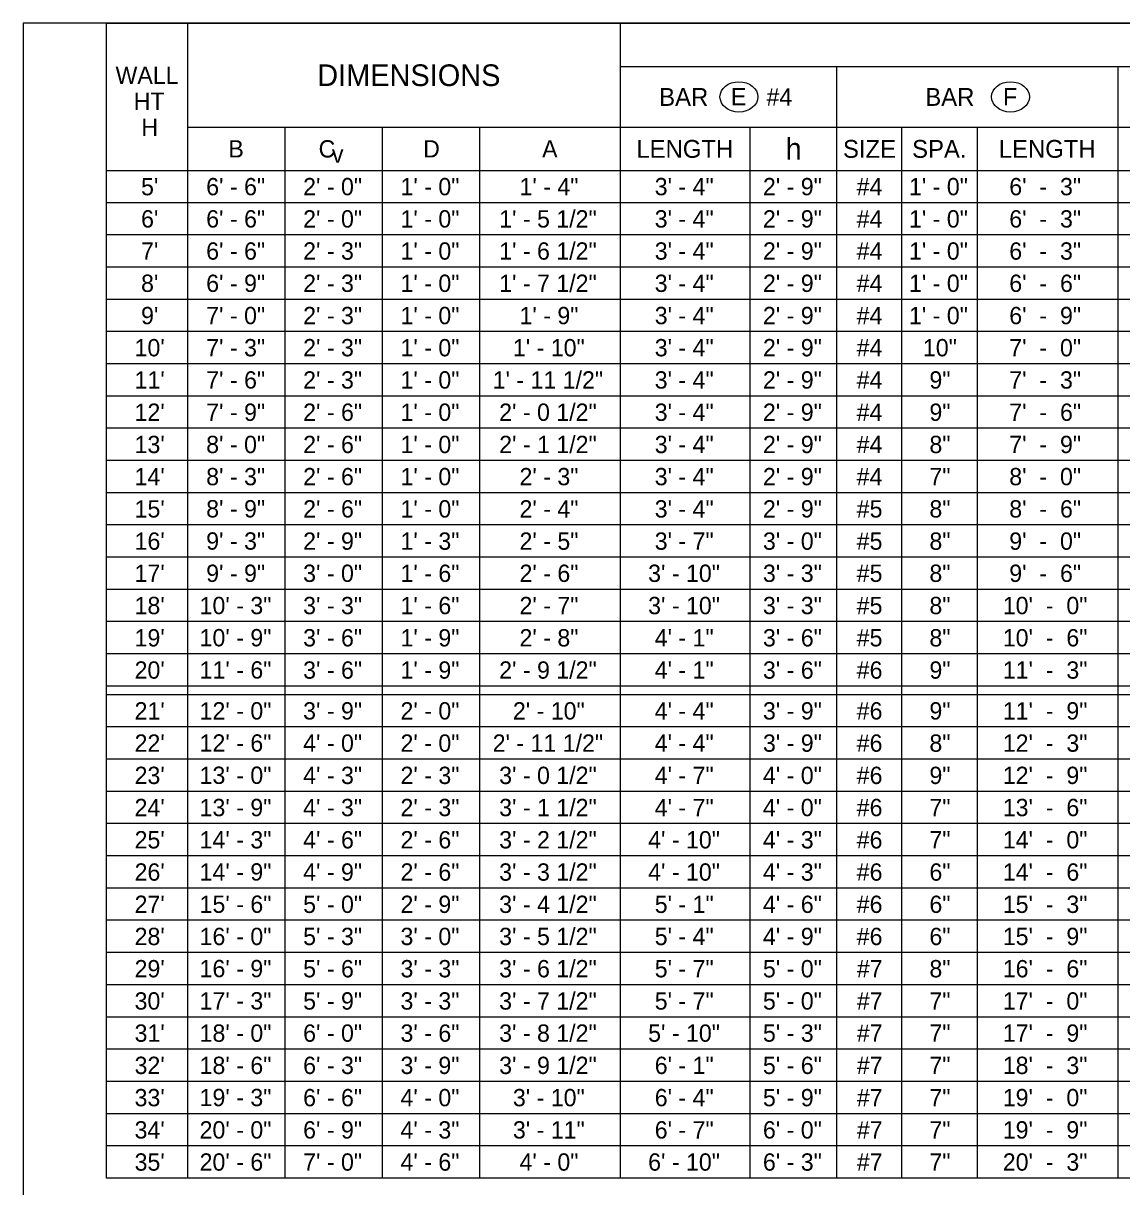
# Model space of a CAD drawing. Extents: x 99862 to 103151, y 100000 to 105076.
# Drawn here: x 99862 to 100877, y 104001 to 105076 of the extents above; entities that cross this region are included whole.
import ezdxf

# ---------------------------------------------------------------- set-up
doc = ezdxf.new("R2010")
doc.units = 0
for name, color, linetype in [('Level 1', 7, 'Continuous'), ('Level 20', 7, 'Continuous'), ('Level 4', 7, 'Continuous')]:
    doc.layers.add(name, color=color, linetype=linetype)

msp = doc.modelspace()

# ---------------------------------------------------------------- linework, layer by layer
at = {"layer": 'Level 1'}
msp.add_lwpolyline([(99862, 102999.5), (103151, 102999.5), (103151, 105075.5), (99862, 105075.5)], close=True, dxfattribs=at)
at = {"layer": 'Level 20'}
for centre in [(100523.5, 105007.5), (100774.5, 105007.5)]:
    msp.add_ellipse(centre, major_axis=(-17.5, 0), ratio=0.8, dxfattribs=at)
at = {"layer": 'Level 4'}
for p, q in [((100014, 104008.6), (100014, 105075.5)), ((100414, 104008.6), (100414, 105075.5)), ((100414, 105035.5), (102554, 105035.5)), ((100614, 104008.6), (100614, 105035.5)), ((100874, 104008.6), (100874, 105035.5)), ((100014, 104979.5), (102711, 104979.5)), ((100104, 104008.6), (100104, 104979.5)), ((100194, 104008.6), (100194, 104979.5)), ((100284, 104008.6), (100284, 104979.5)), ((100534, 104008.6), (100534, 104979.5)), ((100674, 104008.6), (100674, 104979.5)), ((100744, 104008.6), (100744, 104979.5)), ((99939, 104939.5), (103151, 104939.5)), ((103151, 104909.7), (99939, 104909.7)), ((103151, 104880), (99939, 104880)), ((103151, 104850.2), (99939, 104850.2)), ((103151, 104820.4), (99939, 104820.4)), ((103151, 104790.6), (99939, 104790.6)), ((103151, 104760.9), (99939, 104760.9)), ((103151, 104731.1), (99939, 104731.1)), ((103151, 104701.3), (99939, 104701.3)), ((103151, 104671.6), (99939, 104671.6)), ((103151, 104641.8), (99939, 104641.8)), ((103151, 104612), (99939, 104612)), ((103151, 104582.2), (99939, 104582.2)), ((103151, 104552.5), (99939, 104552.5)), ((103151, 104522.7), (99939, 104522.7)), ((103151, 104492.9), (99939, 104492.9)), ((103151, 104463.2), (99939, 104463.2)), ((103151, 104455.2), (99939, 104455.2)), ((103151, 104425.4), (99939, 104425.4)), ((103151, 104395.6), (99939, 104395.6)), ((103151, 104365.8), (99939, 104365.8)), ((103151, 104336.1), (99939, 104336.1)), ((103151, 104306.3), (99939, 104306.3)), ((103151, 104276.5), (99939, 104276.5)), ((103151, 104246.8), (99939, 104246.8)), ((103151, 104217), (99939, 104217)), ((103151, 104187.2), (99939, 104187.2)), ((103151, 104157.4), (99939, 104157.4)), ((103151, 104127.7), (99939, 104127.7)), ((103151, 104097.9), (99939, 104097.9)), ((103151, 104068.1), (99939, 104068.1)), ((103151, 104038.4), (99939, 104038.4))]:
    msp.add_line(p, q, dxfattribs=at)
for points in [[(99939, 105075.5), (103151, 105075.5)], [(103151, 104008.6), (99939, 104008.6), (99939, 105075.5)]]:
    msp.add_lwpolyline(points, dxfattribs=at)

# ---------------------------------------------------------------- texts
at = {"layer": 'Level 20'}
for s, height, p in [('WALL', 16, (99947.3, 105019.5)), ('DIMENSIONS', 20, (100133.7, 105017.5)), ('HT', 16, (99964.1, 104995.5)), ('BAR', 16.5, (100449.8, 104999.2)), ('E', 16, (100516.1, 104999.7)), ('#4', 16, (100549, 104999.5)), ('BAR', 16.5, (100695.8, 104999.2)), ('F', 16, (100767.7, 104999.7)), ('H', 16, (99971.2, 104971.5)), ('C', 16, (100135, 104951.5)), ('LENGTH', 16.5, (100428.7, 104951.2)), ('h', 20, (100566.6, 104949.5)), ('SIZE', 16.5, (100619.7, 104951.2)), ('SPA.', 16.5, (100683.6, 104951.2)), ('LENGTH', 16.5, (100763.7, 104951.2)), ('B', 16, (100051.6, 104951.5)), ('v', 16, (100147.3, 104946.6)), ('D', 16, (100231.6, 104951.5)), ('A', 16, (100341.6, 104951.5)), ("5'", 16, (99970.9, 104916.6)), ('6\' - 6"', 16, (100031.1, 104916.6)), ('2\' - 0"', 16, (100120.7, 104916.6)), ('1\' - 0"', 16, (100210.7, 104916.6)), ('1\' - 4"', 16, (100320.7, 104916.6)), ('2\' - 9"', 16, (100545.7, 104916.6)), ('1\' - 5 1/2"', 16, (100301.9, 104886.8)), ("6'", 16, (99970.9, 104886.8)), ('6\' - 6"', 16, (100031.1, 104886.8)), ('2\' - 0"', 16, (100120.7, 104886.8)), ('1\' - 0"', 16, (100210.7, 104886.8)), ('2\' - 9"', 16, (100545.7, 104886.8)), ("7'", 16, (99970.9, 104857.1)), ('6\' - 6"', 16, (100031.1, 104857.1)), ('2\' - 3"', 16, (100120.7, 104857.1)), ('1\' - 0"', 16, (100210.7, 104857.1)), ('1\' - 6 1/2"', 16, (100301.9, 104857.1)), ('2\' - 9"', 16, (100545.7, 104857.1)), ("8'", 16, (99970.9, 104827.3)), ('6\' - 9"', 16, (100031.1, 104827.3)), ('2\' - 3"', 16, (100120.7, 104827.3)), ('1\' - 0"', 16, (100210.7, 104827.3)), ('1\' - 7 1/2"', 16, (100301.9, 104827.3)), ('2\' - 9"', 16, (100545.7, 104827.3)), ("9'", 16, (99970.9, 104797.5)), ('7\' - 0"', 16, (100031.1, 104797.5)), ('2\' - 3"', 16, (100120.7, 104797.5)), ('1\' - 0"', 16, (100210.7, 104797.5)), ('1\' - 9"', 16, (100320.7, 104797.5)), ('2\' - 9"', 16, (100545.7, 104797.5)), ("10'", 16, (99964.9, 104767.8)), ('7\' - 3"', 16, (100031.1, 104767.8)), ('2\' - 3"', 16, (100120.7, 104767.8)), ('1\' - 0"', 16, (100210.7, 104767.8)), ('1\' - 10"', 16, (100314.6, 104767.8)), ('2\' - 9"', 16, (100545.7, 104767.8)), ("11'", 16, (99964.9, 104738)), ('7\' - 6"', 16, (100031.1, 104738)), ('2\' - 3"', 16, (100120.7, 104738)), ('1\' - 0"', 16, (100210.7, 104738)), ('1\' - 11 1/2"', 16, (100295.9, 104738)), ('2\' - 9"', 16, (100545.7, 104738)), ("12'", 16, (99964.9, 104708.2)), ('7\' - 9"', 16, (100031.1, 104708.2)), ('2\' - 6"', 16, (100120.7, 104708.2)), ('1\' - 0"', 16, (100210.7, 104708.2)), ('2\' - 0 1/2"', 16, (100301.9, 104708.2)), ('2\' - 9"', 16, (100545.7, 104708.2)), ("13'", 16, (99964.9, 104678.4)), ('8\' - 0"', 16, (100031.1, 104678.4)), ('2\' - 6"', 16, (100120.7, 104678.4)), ('1\' - 0"', 16, (100210.7, 104678.4)), ('2\' - 1 1/2"', 16, (100301.9, 104678.4)), ('2\' - 9"', 16, (100545.7, 104678.4)), ("14'", 16, (99964.9, 104648.7)), ('8\' - 3"', 16, (100031.1, 104648.7)), ('2\' - 6"', 16, (100120.7, 104648.7)), ('1\' - 0"', 16, (100210.7, 104648.7)), ('2\' - 3"', 16, (100320.7, 104648.7)), ('2\' - 9"', 16, (100545.7, 104648.7)), ("15'", 16, (99964.9, 104618.9)), ('8\' - 9"', 16, (100031.1, 104619)), ('2\' - 6"', 16, (100120.7, 104618.9)), ('1\' - 0"', 16, (100210.7, 104618.9)), ('2\' - 4"', 16, (100320.7, 104618.9)), ('2\' - 9"', 16, (100545.7, 104618.9)), ("16'", 16, (99964.9, 104589.1)), ('9\' - 3"', 16, (100031.1, 104589.2)), ('2\' - 9"', 16, (100120.7, 104589.1)), ('1\' - 3"', 16, (100210.7, 104589.1)), ('2\' - 5"', 16, (100320.7, 104589.1)), ('3\' - 0"', 16, (100545.7, 104589.1)), ("17'", 16, (99964.9, 104559.4)), ('9\' - 9"', 16, (100031.1, 104559.4)), ('3\' - 0"', 16, (100120.7, 104559.4)), ('1\' - 6"', 16, (100210.7, 104559.4)), ('2\' - 6"', 16, (100320.7, 104559.4)), ('3\' - 3"', 16, (100545.7, 104559.4)), ("18'", 16, (99964.9, 104529.6)), ('10\' - 3"', 16, (100025, 104529.6)), ('3\' - 3"', 16, (100120.7, 104529.6)), ('1\' - 6"', 16, (100210.7, 104529.6)), ('2\' - 7"', 16, (100320.7, 104529.6)), ('3\' - 3"', 16, (100545.7, 104529.6)), ("19'", 16, (99964.9, 104499.8)), ('10\' - 9"', 16, (100025, 104499.9)), ('3\' - 6"', 16, (100120.7, 104499.8)), ('1\' - 9"', 16, (100210.7, 104499.8)), ('2\' - 8"', 16, (100320.7, 104499.8)), ('3\' - 6"', 16, (100545.7, 104499.8)), ("20'", 16, (99964.9, 104470)), ('11\' - 6"', 16, (100025, 104470.1)), ('3\' - 6"', 16, (100120.7, 104470)), ('1\' - 9"', 16, (100210.7, 104470)), ('2\' - 9 1/2"', 16, (100301.9, 104470)), ('3\' - 6"', 16, (100545.7, 104470)), ("21'", 16, (99964.9, 104432.3)), ('12\' - 0"', 16, (100025, 104432.3)), ('3\' - 9"', 16, (100120.7, 104432.3)), ('2\' - 0"', 16, (100210.7, 104432.3)), ('2\' - 10"', 16, (100314.6, 104432.3)), ('3\' - 9"', 16, (100545.7, 104432.3)), ("22'", 16, (99964.9, 104402.5)), ('12\' - 6"', 16, (100025, 104402.6)), ('4\' - 0"', 16, (100120.7, 104402.5)), ('2\' - 0"', 16, (100210.7, 104402.5)), ('2\' - 11 1/2"', 16, (100295.9, 104402.5)), ('3\' - 9"', 16, (100545.7, 104402.5)), ("23'", 16, (99964.9, 104372.7)), ('13\' - 0"', 16, (100025, 104372.8)), ('4\' - 3"', 16, (100120.7, 104372.7)), ('2\' - 3"', 16, (100210.7, 104372.7)), ('3\' - 0 1/2"', 16, (100301.9, 104372.7)), ('4\' - 0"', 16, (100545.7, 104372.7)), ("24'", 16, (99964.9, 104343)), ('13\' - 9"', 16, (100025, 104343)), ('4\' - 3"', 16, (100120.7, 104343)), ('2\' - 3"', 16, (100210.7, 104343)), ('3\' - 1 1/2"', 16, (100301.9, 104343)), ('4\' - 0"', 16, (100545.7, 104343)), ("25'", 16, (99964.9, 104313.2)), ('14\' - 3"', 16, (100025, 104313.2)), ('4\' - 6"', 16, (100120.7, 104313.2)), ('2\' - 6"', 16, (100210.7, 104313.2)), ('3\' - 2 1/2"', 16, (100301.9, 104313.2)), ('4\' - 3"', 16, (100545.7, 104313.2)), ("26'", 16, (99964.9, 104283.4)), ('14\' - 9"', 16, (100025, 104283.5)), ('4\' - 9"', 16, (100120.7, 104283.4)), ('2\' - 6"', 16, (100210.7, 104283.4)), ('3\' - 3 1/2"', 16, (100301.9, 104283.4)), ('4\' - 3"', 16, (100545.7, 104283.4)), ("27'", 16, (99964.9, 104253.6)), ('15\' - 6"', 16, (100025, 104253.7)), ('5\' - 0"', 16, (100120.7, 104253.6)), ('2\' - 9"', 16, (100210.7, 104253.6)), ('3\' - 4 1/2"', 16, (100301.9, 104253.6)), ('4\' - 6"', 16, (100545.7, 104253.6)), ("28'", 16, (99964.9, 104223.9)), ('16\' - 0"', 16, (100025, 104223.9)), ('5\' - 3"', 16, (100120.7, 104223.9)), ('3\' - 0"', 16, (100210.7, 104223.9)), ('3\' - 5 1/2"', 16, (100301.9, 104223.9)), ('4\' - 9"', 16, (100545.7, 104223.9)), ("29'", 16, (99964.9, 104194.1)), ('16\' - 9"', 16, (100025, 104194.2)), ('5\' - 6"', 16, (100120.7, 104194.1)), ('3\' - 3"', 16, (100210.7, 104194.1)), ('3\' - 6 1/2"', 16, (100301.9, 104194.1)), ('5\' - 0"', 16, (100545.7, 104194.1)), ("30'", 16, (99964.9, 104164.3)), ('17\' - 3"', 16, (100025, 104164.4)), ('5\' - 9"', 16, (100120.7, 104164.3)), ('3\' - 3"', 16, (100210.7, 104164.3)), ('3\' - 7 1/2"', 16, (100301.9, 104164.3)), ('5\' - 0"', 16, (100545.7, 104164.3)), ('18\' - 0"', 16, (100025, 104134.6)), ('3\' - 8 1/2"', 16, (100301.9, 104134.6)), ("31'", 16, (99964.9, 104134.6)), ('6\' - 0"', 16, (100120.7, 104134.6)), ('3\' - 6"', 16, (100210.7, 104134.6)), ('5\' - 3"', 16, (100545.7, 104134.6)), ("32'", 16, (99964.9, 104104.8)), ('18\' - 6"', 16, (100025, 104104.8)), ('6\' - 3"', 16, (100120.7, 104104.8)), ('3\' - 9"', 16, (100210.7, 104104.8)), ('3\' - 9 1/2"', 16, (100301.9, 104104.8)), ('5\' - 6"', 16, (100545.7, 104104.8)), ("33'", 16, (99964.9, 104075)), ('19\' - 3"', 16, (100025, 104075.1)), ('6\' - 6"', 16, (100120.7, 104075)), ('4\' - 0"', 16, (100210.7, 104075)), ('3\' - 10"', 16, (100314.6, 104075)), ('5\' - 9"', 16, (100545.7, 104075)), ("34'", 16, (99964.9, 104045.2)), ('20\' - 0"', 16, (100025, 104045.2)), ('6\' - 9"', 16, (100120.7, 104045.2)), ('4\' - 3"', 16, (100210.7, 104045.2)), ('3\' - 11"', 16, (100314.6, 104045.2)), ('6\' - 0"', 16, (100545.7, 104045.2)), ("35'", 16, (99964.9, 104015.5)), ('20\' - 6"', 16, (100025, 104015.5)), ('7\' - 0"', 16, (100120.7, 104015.5)), ('4\' - 6"', 16, (100210.7, 104015.5)), ('4\' - 0"', 16, (100320.7, 104015.5)), ('6\' - 3"', 16, (100545.7, 104015.5))]:
    msp.add_text(s, height=height, dxfattribs=at).set_placement(p)
for s, p in [('#4', (100632.4, 104916.6)), ('1\' - 0"', (100680.7, 104916.6)), ('6\'  -  3"', (100773.4, 104916.6)), ('#4', (100632.4, 104886.8)), ('1\' - 0"', (100680.7, 104886.8)), ('6\'  -  3"', (100773.4, 104886.8)), ('#4', (100632.4, 104857.1)), ('1\' - 0"', (100680.7, 104857.1)), ('6\'  -  3"', (100773.4, 104857.1)), ('#4', (100632.4, 104827.3)), ('1\' - 0"', (100680.7, 104827.3)), ('6\'  -  6"', (100773.4, 104827.3)), ('#4', (100632.4, 104797.5)), ('1\' - 0"', (100680.7, 104797.5)), ('6\'  -  9"', (100773.4, 104797.5)), ('#4', (100632.4, 104767.8)), ('10"', (100693.6, 104767.8)), ('7\'  -  0"', (100773.4, 104767.8)), ('#4', (100632.4, 104738)), ('9"', (100699.6, 104738)), ('7\'  -  3"', (100773.4, 104738)), ('#4', (100632.4, 104708.2)), ('9"', (100699.6, 104708.2)), ('7\'  -  6"', (100773.4, 104708.2)), ('#4', (100632.4, 104678.4)), ('8"', (100699.6, 104678.4)), ('7\'  -  9"', (100773.4, 104678.4)), ('#4', (100632.4, 104648.7)), ('7"', (100699.6, 104648.7)), ('8\'  -  0"', (100773.4, 104648.7)), ('#5', (100632.4, 104618.9)), ('8"', (100699.6, 104618.9)), ('8\'  -  6"', (100773.4, 104618.9)), ('#5', (100632.4, 104589.1)), ('8"', (100699.6, 104589.1)), ('9\'  -  0"', (100773.4, 104589.1)), ('#5', (100632.4, 104559.4)), ('8"', (100699.6, 104559.4)), ('9\'  -  6"', (100773.4, 104559.4)), ('#5', (100632.4, 104529.6)), ('8"', (100699.6, 104529.6)), ('10\'  -  0"', (100767.4, 104529.6)), ('#5', (100632.4, 104499.8)), ('8"', (100699.6, 104499.8)), ('10\'  -  6"', (100767.4, 104499.8)), ('#6', (100632.4, 104470)), ('9"', (100699.6, 104470)), ('11\'  -  3"', (100767.4, 104470)), ('#6', (100632.4, 104432.3)), ('9"', (100699.6, 104432.3)), ('11\'  -  9"', (100767.4, 104432.3)), ('#6', (100632.4, 104402.5)), ('8"', (100699.6, 104402.5)), ('12\'  -  3"', (100767.4, 104402.5)), ('#6', (100632.4, 104372.7)), ('9"', (100699.6, 104372.7)), ('12\'  -  9"', (100767.4, 104372.7)), ('#6', (100632.4, 104343)), ('7"', (100699.6, 104343)), ('13\'  -  6"', (100767.4, 104343)), ('#6', (100632.4, 104313.2)), ('7"', (100699.6, 104313.2)), ('14\'  -  0"', (100767.4, 104313.2)), ('#6', (100632.4, 104283.4)), ('6"', (100699.6, 104283.4)), ('14\'  -  6"', (100767.4, 104283.4)), ('#6', (100632.4, 104253.6)), ('6"', (100699.6, 104253.6)), ('15\'  -  3"', (100767.4, 104253.6)), ('#6', (100632.4, 104223.9)), ('6"', (100699.6, 104223.9)), ('15\'  -  9"', (100767.4, 104223.9)), ('#7', (100632.5, 104194.1)), ('8"', (100699.6, 104194.1)), ('16\'  -  6"', (100767.4, 104194.1)), ('#7', (100632.5, 104164.3)), ('7"', (100699.6, 104164.3)), ('17\'  -  0"', (100767.4, 104164.3)), ('#7', (100632.5, 104134.6)), ('7"', (100699.6, 104134.6)), ('17\'  -  9"', (100767.4, 104134.6)), ('#7', (100632.5, 104104.8)), ('7"', (100699.6, 104104.8)), ('18\'  -  3"', (100767.4, 104104.8)), ('#7', (100632.5, 104075)), ('7"', (100699.6, 104075)), ('19\'  -  0"', (100767.4, 104075)), ('#7', (100632.5, 104045.2)), ('7"', (100699.6, 104045.2)), ('19\'  -  9"', (100767.4, 104045.2)), ('#7', (100632.5, 104015.5)), ('7"', (100699.6, 104015.5)), ('20\'  -  3"', (100767.4, 104015.5))]:
    msp.add_text(s, height=16, rotation=360, dxfattribs=at).set_placement(p)
at = {"layer": 'Level 4'}
for s, p in [('3\' - 4"', (100445.7, 104916.6)), ('3\' - 4"', (100445.7, 104886.8)), ('3\' - 4"', (100445.7, 104857.1)), ('3\' - 4"', (100445.7, 104827.3)), ('3\' - 4"', (100445.7, 104797.5)), ('3\' - 4"', (100445.7, 104767.8)), ('3\' - 4"', (100445.7, 104738)), ('3\' - 4"', (100445.7, 104708.2)), ('3\' - 4"', (100445.7, 104678.4)), ('3\' - 4"', (100445.7, 104648.7)), ('3\' - 4"', (100445.7, 104618.9)), ('3\' - 7"', (100445.7, 104589.1)), ('3\' - 10"', (100439.6, 104559.4)), ('3\' - 10"', (100439.6, 104529.6)), ('4\' - 1"', (100445.7, 104499.8)), ('4\' - 1"', (100445.7, 104470)), ('4\' - 4"', (100445.7, 104432.3)), ('4\' - 4"', (100445.7, 104402.5)), ('4\' - 7"', (100445.7, 104372.7)), ('4\' - 7"', (100445.7, 104343)), ('4\' - 10"', (100439.6, 104313.2)), ('4\' - 10"', (100439.6, 104283.4)), ('5\' - 1"', (100445.7, 104253.6)), ('5\' - 4"', (100445.7, 104223.9)), ('5\' - 7"', (100445.7, 104194.1)), ('5\' - 7"', (100445.7, 104164.3)), ('5\' - 10"', (100439.6, 104134.6)), ('6\' - 1"', (100445.7, 104104.8)), ('6\' - 4"', (100445.7, 104075)), ('6\' - 7"', (100445.7, 104045.2)), ('6\' - 10"', (100439.6, 104015.5))]:
    msp.add_text(s, height=16, dxfattribs=at).set_placement(p)

doc.saveas('drawing.dxf')
